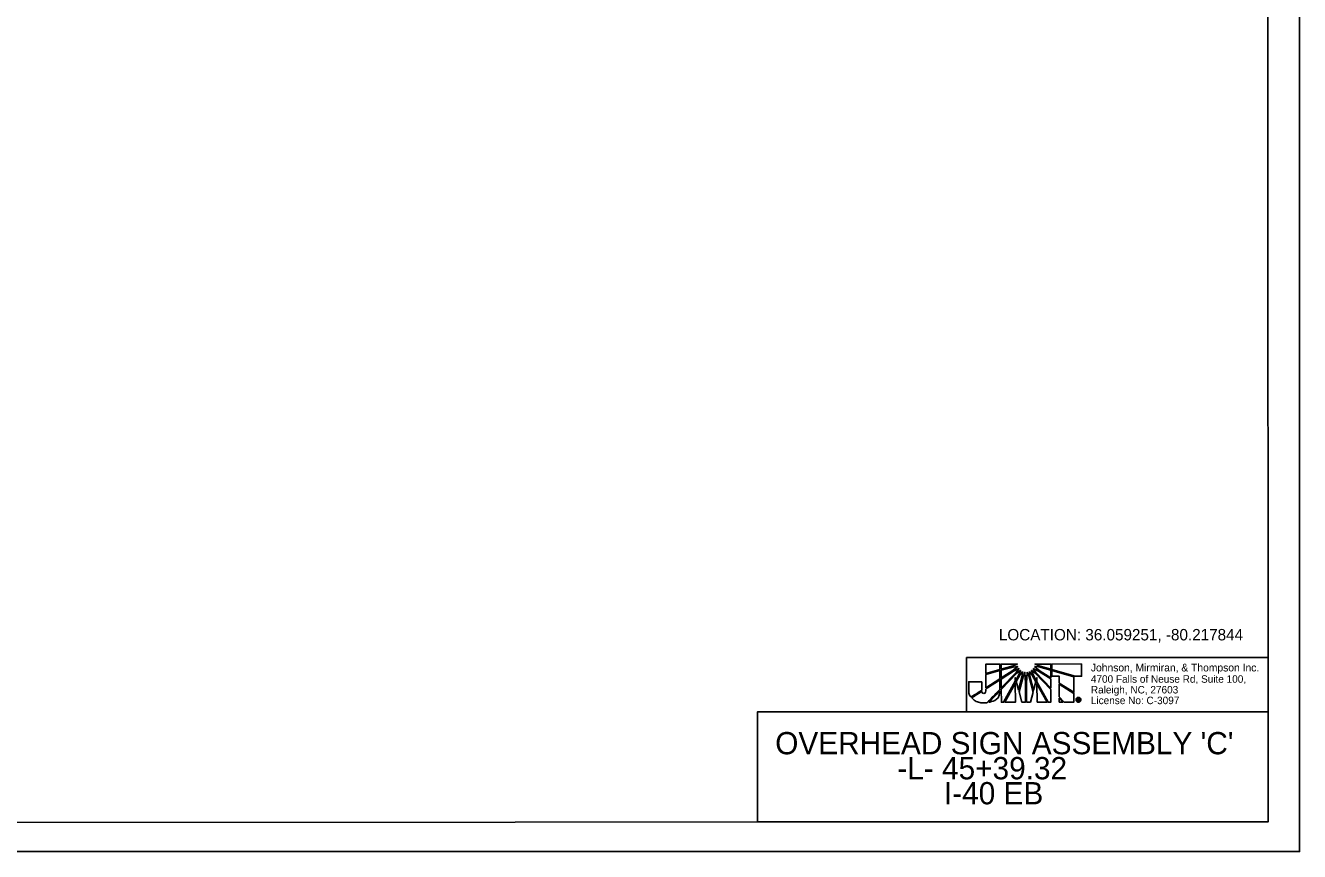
# Model space of a CAD drawing. Extents: x 1725232 to 1728895, y 538685 to 540544.
# Drawn here: x 1725399.8 to 1725568.8, y 539295.4 to 539405 of the extents above; entities that cross this region are included whole.
import ezdxf

# ---------------------------------------------------------------- set-up
doc = ezdxf.new("R2010")
doc.units = 0
for name, color, linetype in [('Default', 7, 'Continuous'), ('DEV BORDER CELL', 7, 'Continuous'), ('Overhead Sheet Border', 7, 'Continuous'), ('Overhead Sheet Box', 7, 'Continuous'), ('Overhead Sheet Text', 7, 'Continuous'), ('Sheet Plot Border Outside CELL', 7, 'Continuous'), ('Sheet Sticker Exception Certification CELL', 7, 'Continuous')]:
    doc.layers.add(name, color=color, linetype=linetype)

msp = doc.modelspace()

# ---------------------------------------------------------------- linework, layer by layer
at = {"layer": 'Default'}
for p, q in [((1725529.09, 539320.23), (1725527.21, 539320.22)), ((1725527.21, 539320.22), (1725527.22, 539318.98)), ((1725529.09, 539319.5), (1725529.09, 539320.23)), ((1725531.39, 539320.24), (1725529.28, 539320.24)), ((1725529.28, 539320.24), (1725529.28, 539319.57)), ((1725530.85, 539320), (1725531.39, 539320.24)), ((1725535.85, 539320.23), (1725533.77, 539320.24)), ((1725533.77, 539320.24), (1725534.3, 539319.99)), ((1725535.85, 539319.56), (1725535.85, 539320.23)), ((1725539.93, 539320.25), (1725535.99, 539320.24)), ((1725535.99, 539320.24), (1725536, 539319.52)), ((1725539.93, 539318.63), (1725539.93, 539320.25)), ((1725527.22, 539318.98), (1725529.09, 539319.5)), ((1725529.09, 539319.37), (1725527.22, 539318.84)), ((1725527.22, 539318.84), (1725527.22, 539317.09)), ((1725529.09, 539318.28), (1725529.09, 539319.37)), ((1725529.28, 539319.57), (1725530.85, 539320)), ((1725530.85, 539319.85), (1725529.28, 539319.42)), ((1725529.28, 539319.42), (1725529.28, 539318.41)), ((1725529.28, 539318.41), (1725530.69, 539319.3)), ((1725530.9, 539319.28), (1725529.28, 539318.24)), ((1725529.28, 539317.08), (1725531.26, 539319.13)), ((1725531.34, 539319.03), (1725529.28, 539316.88)), ((1725530.69, 539319.3), (1725531.46, 539319.93)), ((1725531.46, 539319.93), (1725530.85, 539319.85)), ((1725531.62, 539319.64), (1725530.9, 539319.28)), ((1725531.12, 539317.95), (1725531.12, 539318.44)), ((1725531.12, 539318.44), (1725531.21, 539318.1)), ((1725531.21, 539318.1), (1725531.61, 539318.81)), ((1725531.26, 539319.13), (1725531.62, 539319.64)), ((1725531.73, 539318.77), (1725531.27, 539317.92)), ((1725531.83, 539319.41), (1725531.34, 539319.03)), ((1725531.57, 539316.8), (1725532.05, 539318.67)), ((1725531.61, 539318.81), (1725531.83, 539319.41)), ((1725532.16, 539318.56), (1725531.63, 539316.54)), ((1725532.1, 539319.25), (1725531.73, 539318.77)), ((1725532.05, 539318.67), (1725532.1, 539319.25)), ((1725532.41, 539319.16), (1725532.16, 539318.56)), ((1725532.49, 539317.69), (1725532.41, 539319.16)), ((1725532.72, 539319.16), (1725532.63, 539317.69)), ((1725532.97, 539318.56), (1725532.72, 539319.16)), ((1725533.51, 539316.51), (1725532.97, 539318.56)), ((1725533.02, 539319.25), (1725533.08, 539318.65)), ((1725533.38, 539318.77), (1725533.02, 539319.25)), ((1725533.08, 539318.65), (1725533.57, 539316.76)), ((1725533.29, 539319.41), (1725533.52, 539318.82)), ((1725533.78, 539319.03), (1725533.29, 539319.41)), ((1725533.87, 539317.9), (1725533.38, 539318.77)), ((1725533.51, 539319.64), (1725533.87, 539319.12)), ((1725534.23, 539319.28), (1725533.51, 539319.64)), ((1725533.52, 539318.82), (1725533.92, 539318.07)), ((1725533.67, 539319.93), (1725534.45, 539319.29)), ((1725534.25, 539319.86), (1725533.67, 539319.93)), ((1725535.84, 539316.87), (1725533.78, 539319.03)), ((1725533.87, 539319.12), (1725535.84, 539317.06)), ((1725533.92, 539318.07), (1725534.01, 539318.44)), ((1725534.01, 539318.44), (1725534.01, 539317.9)), ((1725535.84, 539318.26), (1725534.23, 539319.28)), ((1725535.85, 539319.42), (1725534.25, 539319.86)), ((1725534.3, 539319.99), (1725535.85, 539319.56)), ((1725534.45, 539319.29), (1725535.84, 539318.43)), ((1725535.84, 539318.43), (1725535.85, 539319.42)), ((1725536, 539319.52), (1725536, 539319.5)), ((1725536, 539319.5), (1725539.09, 539318.63)), ((1725536, 539319.39), (1725536, 539319.37)), ((1725538.9, 539318.56), (1725536, 539319.39)), ((1725536, 539319.37), (1725536, 539318.62)), ((1725536, 539318.62), (1725536.96, 539318.62)), ((1725536.96, 539318.62), (1725536.96, 539317.72)), ((1725538.9, 539316.49), (1725538.9, 539318.56)), ((1725539.09, 539318.63), (1725539.93, 539318.63)), ((1725527.22, 539317.09), (1725529.09, 539318.28)), ((1725529.28, 539318.24), (1725529.28, 539317.08)), ((1725529.28, 539316.88), (1725529.29, 539315.18)), ((1725529.59, 539315.18), (1725531.12, 539317.95)), ((1725531.12, 539317.68), (1725529.74, 539315.18)), ((1725531.14, 539315.18), (1725531.12, 539317.68)), ((1725531.27, 539317.92), (1725531.57, 539316.8)), ((1725532.5, 539315.19), (1725532.49, 539317.69)), ((1725532.63, 539317.69), (1725532.63, 539315.19)), ((1725533.57, 539316.76), (1725533.87, 539317.9)), ((1725534.01, 539317.9), (1725535.51, 539315.18)), ((1725535.36, 539315.19), (1725534.01, 539317.63)), ((1725534.01, 539317.63), (1725534.02, 539315.19)), ((1725535.84, 539317.06), (1725535.84, 539318.26)), ((1725535.84, 539315.18), (1725535.84, 539316.87)), ((1725536.96, 539317.72), (1725538.9, 539316.49)), ((1725536.96, 539317.57), (1725536.96, 539315.89)), ((1725538.9, 539316.35), (1725536.96, 539317.57)), ((1725529.29, 539315.18), (1725529.59, 539315.18)), ((1725529.74, 539315.18), (1725531.14, 539315.18)), ((1725531.63, 539316.54), (1725531.98, 539315.19)), ((1725531.98, 539315.19), (1725532.5, 539315.19)), ((1725532.63, 539315.19), (1725533.15, 539315.19)), ((1725533.15, 539315.19), (1725533.51, 539316.51)), ((1725534.02, 539315.19), (1725535.36, 539315.19)), ((1725535.51, 539315.18), (1725535.84, 539315.18)), ((1725536.96, 539315.89), (1725537.63, 539315.19)), ((1725537.45, 539315.19), (1725536.96, 539315.71)), ((1725536.96, 539315.71), (1725536.96, 539315.19)), ((1725536.96, 539315.19), (1725537.45, 539315.19)), ((1725537.63, 539315.19), (1725538.9, 539315.19)), ((1725538.9, 539315.19), (1725538.9, 539316.35)), ((1725539.39, 539315.36), (1725539.39, 539315.65)), ((1725539.39, 539315.65), (1725539.51, 539315.65)), ((1725539.46, 539315.36), (1725539.39, 539315.36)), ((1725539.51, 539315.6), (1725539.46, 539315.6)), ((1725539.46, 539315.6), (1725539.46, 539315.53)), ((1725539.46, 539315.53), (1725539.51, 539315.53)), ((1725539.51, 539315.48), (1725539.46, 539315.48)), ((1725539.46, 539315.48), (1725539.46, 539315.36)), ((1725539.51, 539315.82), (1725539.51, 539315.76)), ((1725539.51, 539315.76), (1725539.51, 539315.82)), ((1725539.51, 539315.65), (1725539.51, 539315.6)), ((1725539.51, 539315.6), (1725539.51, 539315.65)), ((1725539.51, 539315.65), (1725539.53, 539315.65)), ((1725539.52, 539315.6), (1725539.51, 539315.6)), ((1725539.51, 539315.53), (1725539.51, 539315.48)), ((1725539.51, 539315.48), (1725539.51, 539315.53)), ((1725539.51, 539315.53), (1725539.51, 539315.53)), ((1725539.51, 539315.48), (1725539.51, 539315.48)), ((1725539.51, 539315.25), (1725539.51, 539315.19)), ((1725539.51, 539315.19), (1725539.51, 539315.25)), ((1725539.51, 539315.25), (1725539.51, 539315.25)), ((1725539.51, 539315.19), (1725539.51, 539315.19))]:
    msp.add_line(p, q, dxfattribs=at)
msp.add_lwpolyline([(1725524.68, 539313.89), (1725564.69, 539313.89), (1725564.69, 539321.11), (1725524.68, 539321.11)], close=True, dxfattribs=at)
for points in [[(1725527.22, 539318.98), (1725529.09, 539319.5), (1725529.09, 539320.23), (1725527.21, 539320.22), (1725527.22, 539318.98)], [(1725530.85, 539320), (1725531.39, 539320.24), (1725529.28, 539320.24), (1725529.28, 539319.57), (1725530.85, 539320)], [(1725534.3, 539319.99), (1725535.85, 539319.56), (1725535.85, 539320.23), (1725533.77, 539320.24), (1725534.3, 539319.99)], [(1725539.93, 539320.25), (1725535.99, 539320.24), (1725536, 539319.52), (1725536, 539319.5), (1725539.09, 539318.63), (1725539.93, 539318.63), (1725539.93, 539320.25)], [(1725527.22, 539317.09), (1725529.09, 539318.28), (1725529.09, 539319.37), (1725527.22, 539318.84), (1725527.22, 539317.09)], [(1725529.28, 539319.42), (1725529.28, 539318.41), (1725530.69, 539319.3), (1725531.46, 539319.93), (1725530.85, 539319.85), (1725529.28, 539319.42)], [(1725529.28, 539318.24), (1725529.28, 539317.08), (1725531.26, 539319.13), (1725531.62, 539319.64), (1725530.9, 539319.28), (1725529.28, 539318.24)], [(1725531.83, 539319.41), (1725531.34, 539319.03), (1725529.28, 539316.88), (1725529.29, 539315.18), (1725529.59, 539315.18), (1725531.12, 539317.95), (1725531.12, 539318.44), (1725531.21, 539318.1), (1725531.61, 539318.81), (1725531.83, 539319.41)], [(1725532.1, 539319.25), (1725531.73, 539318.77), (1725531.27, 539317.92), (1725531.57, 539316.8), (1725532.05, 539318.67), (1725532.1, 539319.25)], [(1725532.16, 539318.56), (1725531.63, 539316.54), (1725531.98, 539315.19), (1725532.5, 539315.19), (1725532.49, 539317.69), (1725532.41, 539319.16), (1725532.16, 539318.56)], [(1725532.72, 539319.16), (1725532.63, 539317.69), (1725532.63, 539315.19), (1725533.15, 539315.19), (1725533.51, 539316.51), (1725532.97, 539318.56), (1725532.72, 539319.16)], [(1725533.02, 539319.25), (1725533.08, 539318.65), (1725533.57, 539316.76), (1725533.87, 539317.9), (1725533.38, 539318.77), (1725533.02, 539319.25)], [(1725533.29, 539319.41), (1725533.52, 539318.82), (1725533.92, 539318.07), (1725534.01, 539318.44), (1725534.01, 539317.9), (1725535.51, 539315.18), (1725535.84, 539315.18), (1725535.84, 539316.87), (1725533.78, 539319.03), (1725533.29, 539319.41)], [(1725533.51, 539319.64), (1725533.87, 539319.12), (1725535.84, 539317.06), (1725535.84, 539318.26), (1725534.23, 539319.28), (1725533.51, 539319.64)], [(1725533.67, 539319.93), (1725534.45, 539319.29), (1725535.84, 539318.43), (1725535.85, 539319.42), (1725534.25, 539319.86), (1725533.67, 539319.93)], [(1725536, 539319.39), (1725536, 539319.37), (1725536, 539318.62), (1725536.96, 539318.62), (1725536.96, 539317.72), (1725538.9, 539316.49), (1725538.9, 539318.56), (1725536, 539319.39)], [(1725529.74, 539315.18), (1725531.14, 539315.18), (1725531.12, 539317.68), (1725529.74, 539315.18)], [(1725534.02, 539315.19), (1725535.36, 539315.19), (1725534.01, 539317.63), (1725534.02, 539315.19)], [(1725536.96, 539317.57), (1725536.96, 539315.89), (1725537.63, 539315.19), (1725538.9, 539315.19), (1725538.9, 539316.35), (1725536.96, 539317.57), (1725536.96, 539317.57)], [(1725536.96, 539315.19), (1725536.96, 539315.19), (1725537.45, 539315.19), (1725536.96, 539315.71), (1725536.96, 539315.19)], [(1725539.64, 539315.43), (1725539.64, 539315.42), (1725539.64, 539315.41), (1725539.64, 539315.4), (1725539.65, 539315.36), (1725539.59, 539315.36)]]:
    msp.add_lwpolyline(points, dxfattribs=at)
for points, degree in [([(1725526.68, 539317.9), (1725526.68, 539317.9), (1725524.95, 539317.9), (1725524.95, 539317.9), (1725524.95, 539317.9), (1725524.95, 539316.81), (1725524.95, 539316.81), (1725524.95, 539316.81), (1725524.95, 539316.7), (1725524.95, 539316.7), (1725524.95, 539316.36), (1725525.06, 539316.09), (1725525.26, 539315.86), (1725525.26, 539315.86), (1725526.68, 539316.73), (1725526.68, 539316.75), (1725526.68, 539316.75), (1725526.68, 539317.9), (1725526.68, 539317.9)], 3), ([(1725526.95, 539316.34), (1725526.84, 539316.34), (1725526.74, 539316.4), (1725526.7, 539316.61), (1725526.7, 539316.61), (1725525.36, 539315.77), (1725525.36, 539315.77), (1725525.77, 539315.34), (1725526.43, 539315.08), (1725526.99, 539315.08), (1725527.14, 539315.08), (1725527.25, 539315.09), (1725527.4, 539315.12), (1725527.4, 539315.12), (1725529.09, 539316.87), (1725529.09, 539316.87), (1725529.09, 539316.87), (1725529.09, 539318.13), (1725529.09, 539318.13), (1725529.09, 539318.13), (1725527.22, 539316.94), (1725527.22, 539316.94), (1725527.22, 539316.46), (1725527.1, 539316.34), (1725526.95, 539316.34)], 3), ([(1725526.95, 539316.34), (1725526.84, 539316.34), (1725526.74, 539316.4), (1725526.7, 539316.61), (1725526.7, 539316.61), (1725525.36, 539315.77), (1725525.36, 539315.77), (1725525.77, 539315.34), (1725526.43, 539315.08), (1725526.99, 539315.08), (1725527.14, 539315.08), (1725527.25, 539315.09), (1725527.4, 539315.12), (1725527.4, 539315.12), (1725529.09, 539316.87), (1725529.09, 539316.87), (1725529.09, 539316.87), (1725529.09, 539318.13), (1725529.09, 539318.13), (1725529.09, 539318.13), (1725527.22, 539316.94), (1725527.22, 539316.94), (1725527.22, 539316.46), (1725527.1, 539316.34), (1725526.95, 539316.34)], 3), ([(1725529.09, 539316.67), (1725529.09, 539316.67), (1725527.63, 539315.16), (1725527.63, 539315.16), (1725528.35, 539315.34), (1725529.06, 539315.81), (1725529.09, 539316.67)], 3), ([(1725539.51, 539315.19), (1725539.42, 539315.19), (1725539.35, 539315.22), (1725539.29, 539315.28), (1725539.22, 539315.34), (1725539.19, 539315.42), (1725539.19, 539315.51), (1725539.19, 539315.6), (1725539.22, 539315.67), (1725539.29, 539315.73), (1725539.35, 539315.79), (1725539.42, 539315.82), (1725539.51, 539315.82)], 3), ([(1725539.51, 539315.76), (1725539.44, 539315.76), (1725539.38, 539315.74), (1725539.33, 539315.69), (1725539.28, 539315.64), (1725539.26, 539315.58), (1725539.26, 539315.51), (1725539.26, 539315.44), (1725539.28, 539315.37), (1725539.33, 539315.33), (1725539.38, 539315.28), (1725539.44, 539315.25), (1725539.51, 539315.25)], 3), ([(1725539.51, 539315.82), (1725539.6, 539315.82), (1725539.67, 539315.79), (1725539.74, 539315.73), (1725539.8, 539315.67), (1725539.83, 539315.6), (1725539.83, 539315.51)], 3), ([(1725539.51, 539315.25), (1725539.58, 539315.25), (1725539.64, 539315.28), (1725539.69, 539315.33), (1725539.74, 539315.38), (1725539.77, 539315.44), (1725539.77, 539315.51), (1725539.77, 539315.58), (1725539.74, 539315.64), (1725539.69, 539315.69), (1725539.64, 539315.74), (1725539.58, 539315.76), (1725539.51, 539315.76)], 3), ([(1725539.51, 539315.53), (1725539.55, 539315.53), (1725539.58, 539315.54), (1725539.58, 539315.57), (1725539.58, 539315.59), (1725539.56, 539315.6), (1725539.52, 539315.6)], 3), ([(1725539.83, 539315.51), (1725539.83, 539315.42), (1725539.8, 539315.34), (1725539.74, 539315.28), (1725539.68, 539315.22), (1725539.6, 539315.19), (1725539.51, 539315.19)], 3), ([(1725539.56, 539315.47), (1725539.55, 539315.47), (1725539.54, 539315.48), (1725539.51, 539315.48)], 2), ([(1725539.53, 539315.65), (1725539.6, 539315.65), (1725539.64, 539315.62), (1725539.64, 539315.57), (1725539.64, 539315.54), (1725539.63, 539315.52), (1725539.6, 539315.5)], 3), ([(1725539.59, 539315.36), (1725539.58, 539315.38), (1725539.57, 539315.4), (1725539.57, 539315.42), (1725539.57, 539315.44), (1725539.57, 539315.46), (1725539.56, 539315.47)], 3), ([(1725539.6, 539315.5), (1725539.62, 539315.49), (1725539.63, 539315.47), (1725539.64, 539315.43)], 2)]:
    msp.add_open_spline(points, degree=degree, dxfattribs=at)
at = {"layer": 'DEV BORDER CELL'}
msp.add_line((1725568.84, 539295.37), (1725568.84, 539295.37), dxfattribs=at)
at = {"layer": 'Overhead Sheet Border'}
msp.add_lwpolyline([(1725564.58, 539509.16), (1725264.83, 539509), (1725264.95, 539299.17), (1725564.7, 539299.33)], close=True, dxfattribs=at)
at = {"layer": 'Overhead Sheet Box'}
msp.add_lwpolyline([(1725496.93, 539299.33), (1725564.7, 539299.33), (1725564.7, 539313.89), (1725496.93, 539313.89)], close=True, dxfattribs=at)
at = {"layer": 'Sheet Plot Border Outside CELL'}
msp.add_lwpolyline([(1725568.84, 539514.55), (1725232.26, 539514.55), (1725232.26, 539295.37), (1725568.84, 539295.37)], close=True, dxfattribs=at)

# ---------------------------------------------------------------- texts
at = {"layer": 'Default'}
for s, height, p in [('Johnson, Mirmiran, & Thompson Inc.', 1.0222, (1725541.16, 539319.26)), ('4700 Falls of Neuse Rd, Suite 100, ', 0.993, (1725541.16, 539317.76)), ('Raleigh, NC, 27603', 0.993, (1725541.16, 539316.34)), ('License No: C-3097', 0.993, (1725541.16, 539314.92))]:
    msp.add_text(s, height=height, dxfattribs=at).set_placement(p)
at = {"layer": 'Overhead Sheet Text'}
msp.add_text('LOCATION: 36.059251, -80.217844', height=1.5129, dxfattribs=at).set_placement((1725528.96, 539323.38))
at = {"layer": 'Sheet Sticker Exception Certification CELL'}
for s, height, p in [("OVERHEAD SIGN ASSEMBLY 'C'", 2.9546, (1725499.29, 539308.27)), ('-L- 45+39.32', 2.9546, (1725515.49, 539304.95)), ('I-40 EB', 2.955, (1725521.67, 539301.63))]:
    msp.add_text(s, height=height, dxfattribs=at).set_placement(p)

doc.saveas('drawing.dxf')
